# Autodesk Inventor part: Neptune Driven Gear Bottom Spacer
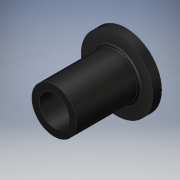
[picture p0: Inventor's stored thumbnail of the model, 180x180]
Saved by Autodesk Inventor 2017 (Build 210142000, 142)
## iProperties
Created: 2016-07
Part Number: Neptune Driven Gear Bottom Spacer
Material: Generic
Document SubType Name: Modeling
Designer: Stan
Density: 1 g/cm^3
Appearance: Glossy - Black
Author: Stan
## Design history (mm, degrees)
sketch "Sketch1"
  geometry: C1 r 12.7 at (0, 0); 1 further point
  constraints: 1 centre point, 1 coincident
  dimensions: "d0" = 25.4 diameter of C1
extrude "Extrusion1" new body sketch "Sketch1" distance "d1" = 3.175; taper "d2" = 0 deg
sketch "Sketch2"
  geometry: C1 r 7.938 at (0, 0); 1 further point
  constraints: 1 centre point, 1 coincident
  dimensions: "d3" = 15.875 diameter of C1
extrude "Extrusion2" join sketch "Sketch2" distance "d4" = 22.225; taper "d5" = 0 deg
sketch "Sketch3"
  geometry: C1 r 5.334 at (0, 0); 1 further point
  constraints: 1 centre point, 1 coincident
  dimensions: "d6" = 10.668 diameter of C1
extrude "Extrusion3" cut sketch "Sketch3" distance "d7" = 25.4; taper "d8" = 0 deg
fillet "Fillet1" dims "d9" = 0.79375
body "Solid1"
